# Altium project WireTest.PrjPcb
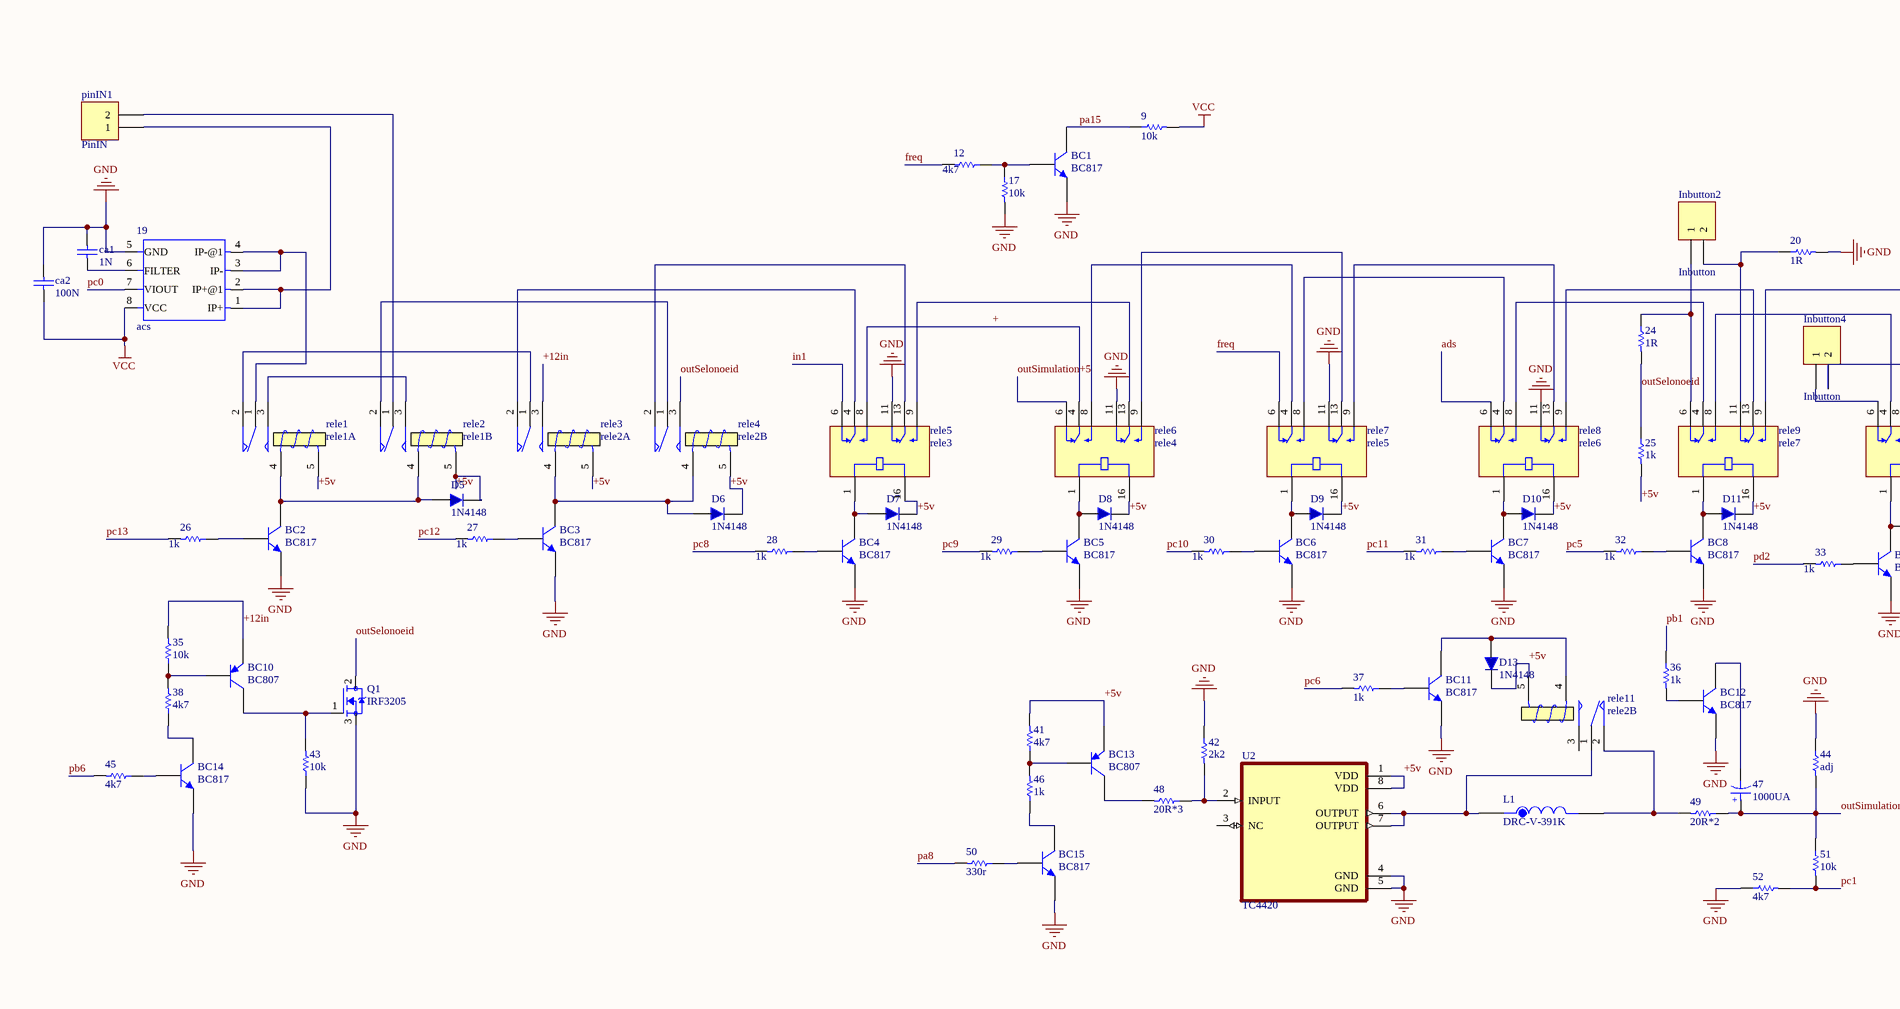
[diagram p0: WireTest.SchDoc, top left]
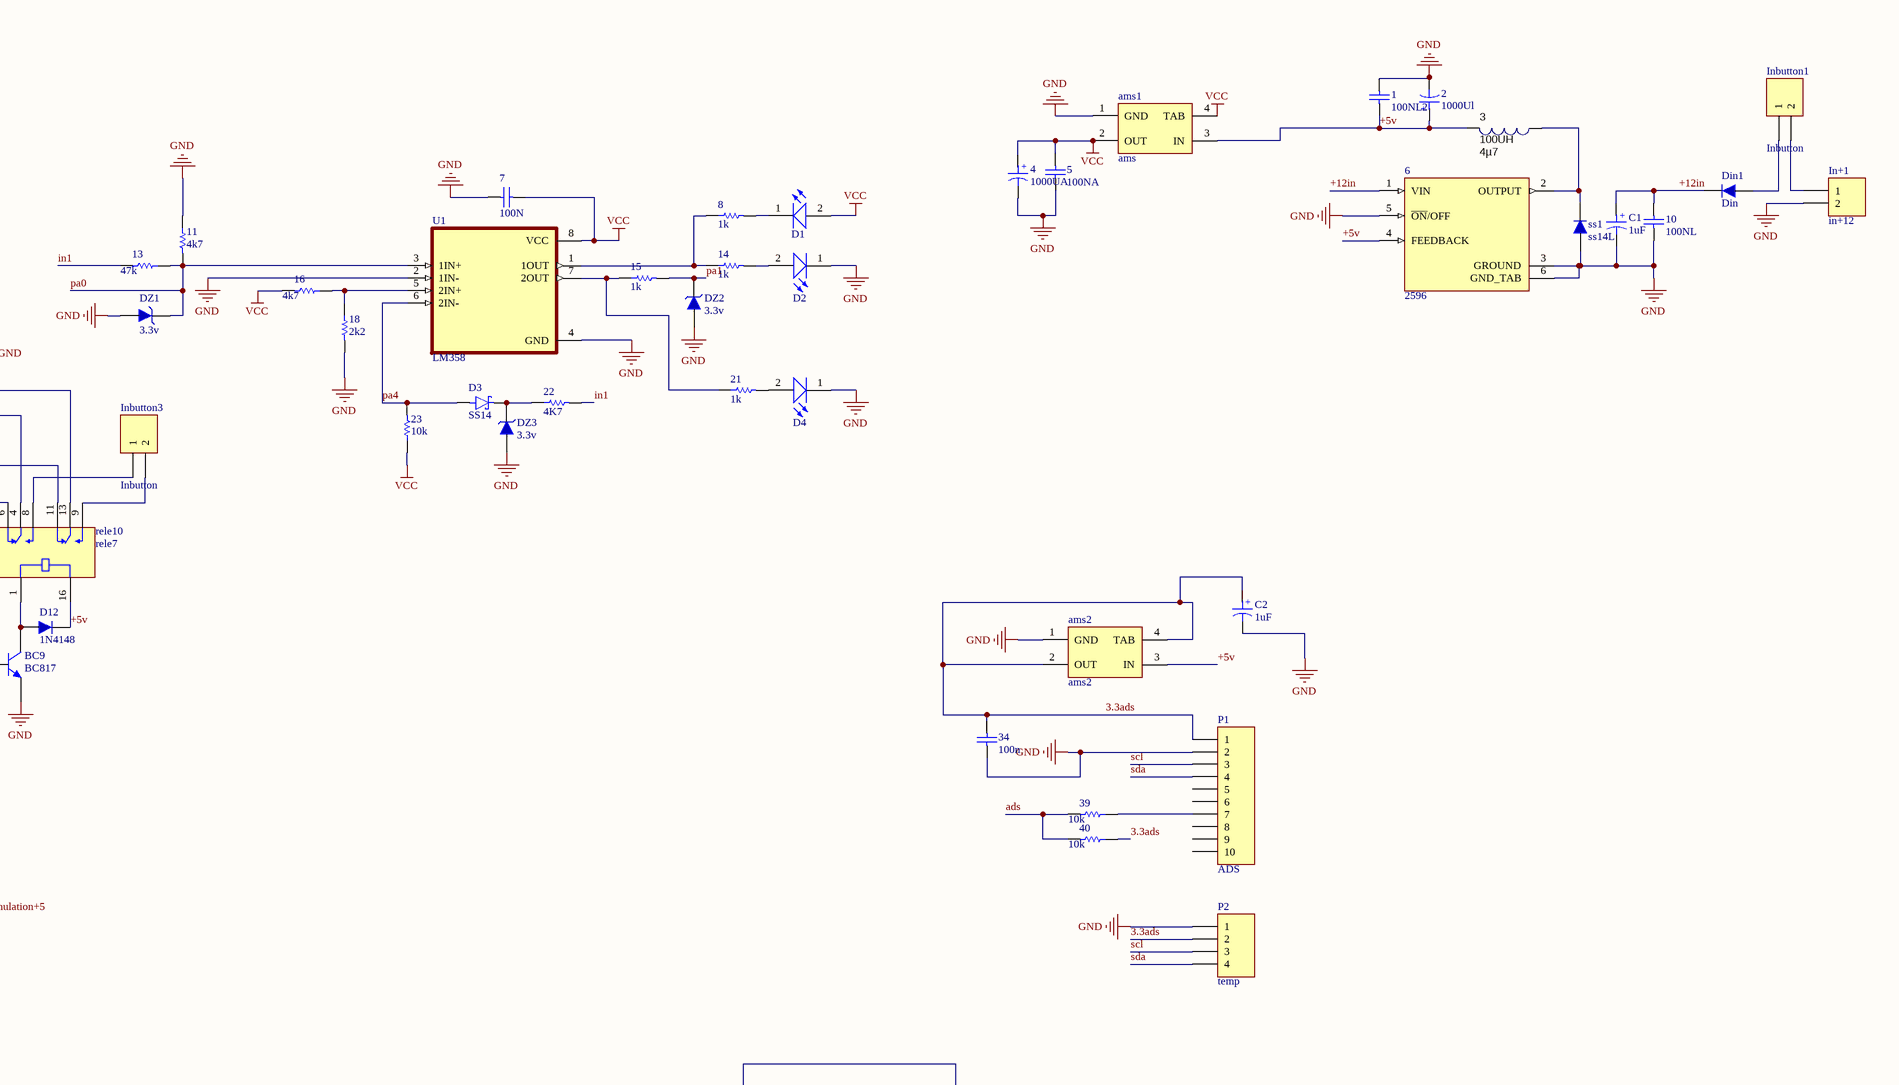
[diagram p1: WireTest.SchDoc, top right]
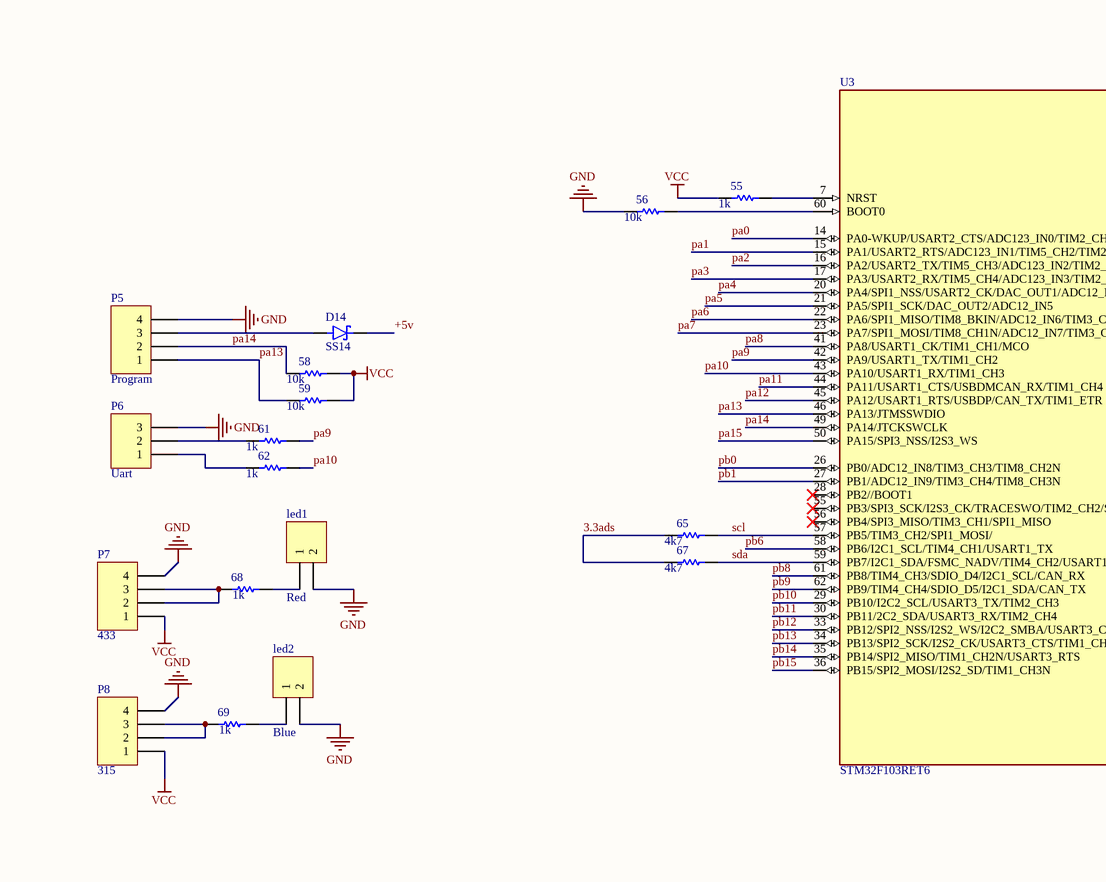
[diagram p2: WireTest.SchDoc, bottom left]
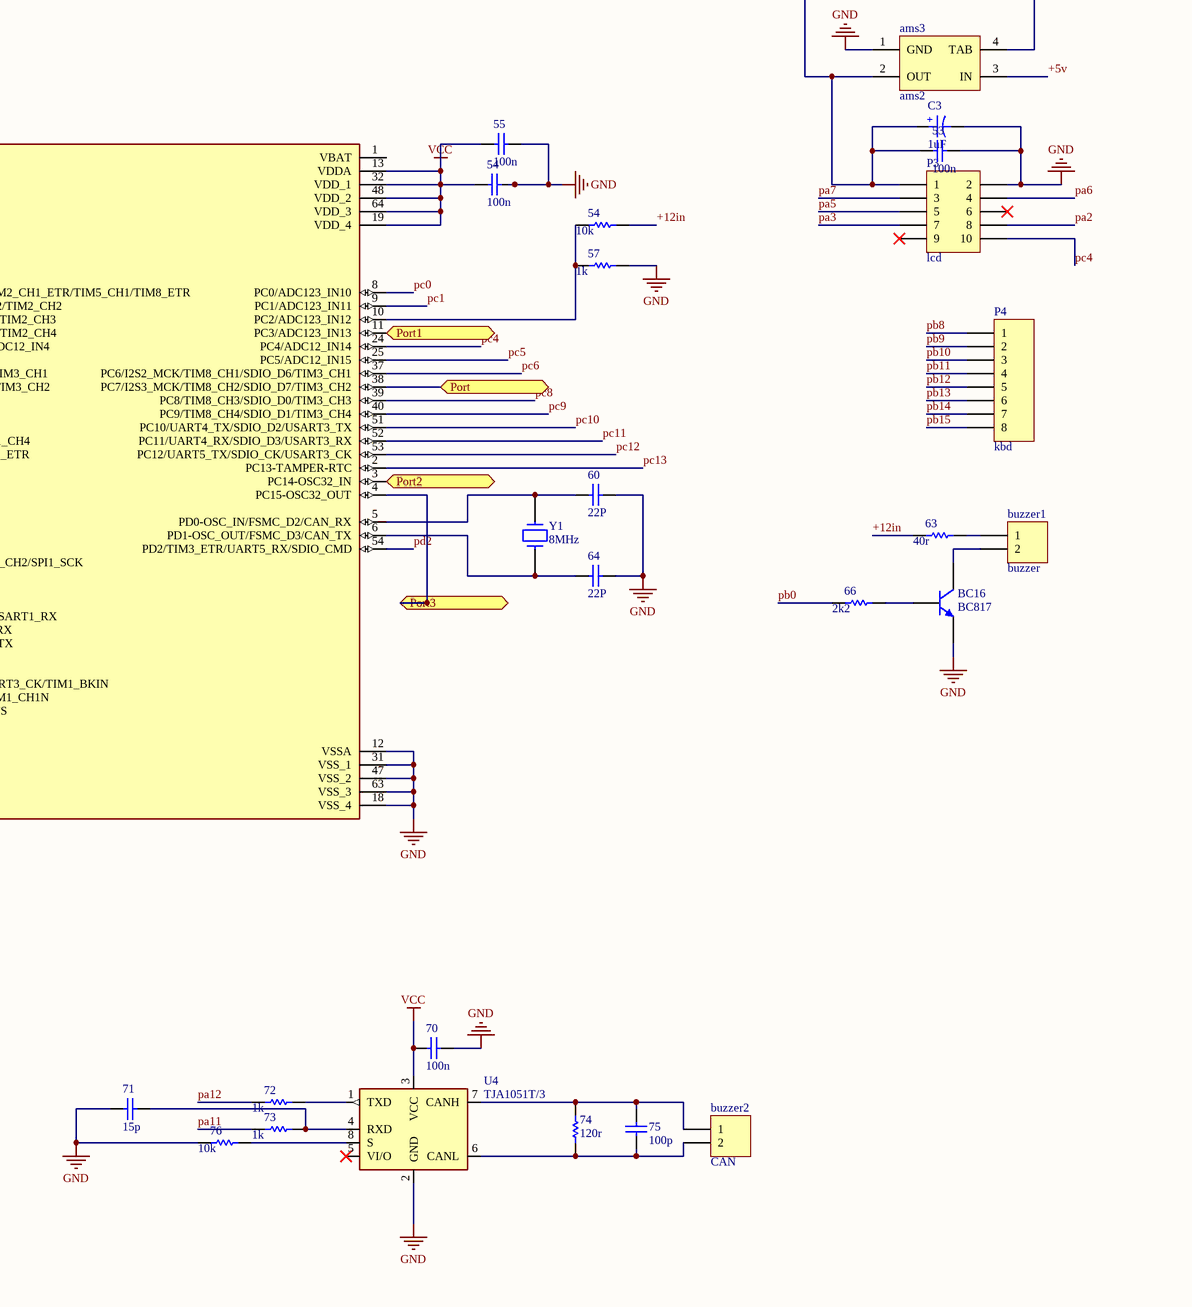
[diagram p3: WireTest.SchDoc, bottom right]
1 sheet, 157 parts. Net scope: flat (ports and power ports of the same name join across sheets).
Board file: wireTest.PcbDoc

## Sheet WireTest.SchDoc
size D

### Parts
(Parts that share a designator on the sheet are numbered #1, #2 ... from top to bottom, then left to right.)
1  100NL2  [CAPC3413X12N]
2  1000Ul  [Cap electrolitic radial 8x12-3.5]
3  100UH  value 4µ7  [Inductor SMD 3x3.2mm]
4  1000UA  [Cap electrolitic radial 8x12-3.5]
5  100NA  [CAPC3413X12N]
6  2596  [TO170P1524X483-6N]
7  100N  [CAPC3413X12N]
8  1k  [RESC4817X04N]
9  10k  [RESC4817X04N]
10  100NL  [CAPC3413X12N]
11  4k7  [RESC4817X04N]
12  4k7  [RESC4817X04N]
13  47k  [RESC4817X04N]
14  1k  [RESC4817X04N]
15  1k  [RESC4817X04N]
16  4k7  [RESC4817X04N]
17  10k  [RESC4817X04N]
18  2k2  [RESC4817X04N]
19  acs  [SOIC8-1.27-5X4MM]
20  1R  [RESC4817X04N]
21  1k  [RESC4817X04N]
22  4K7  [RESC4817X04N]
23  10k  [RESC4817X04N]
24  1R  [RESC4817X04N]
25  1k  [RESC4817X04N]
26  1k  [RESC4817X04N]
27  1k  [RESC4817X04N]
28  1k  [RESC4817X04N]
29  1k  [RESC4817X04N]
30  1k  [RESC4817X04N]
31  1k  [RESC4817X04N]
32  1k  [RESC4817X04N]
33  1k  [RESC4817X04N]
34  100n  [CAPC3413X12N]
35  10k  [RESC4817X04N]
36  1k  [RESC4817X04N]
37  1k  [RESC4817X04N]
38  4k7  [RESC4817X04N]
39  10k  [RESC4817X04N]
40  10k  [RESC4817X04N]
41  4k7  [RESC4817X04N]
42  2k2  [RESC4817X04N]
43  10k  [RESC4817X04N]
44  adj  [RESC4817X04N]
45  4k7  [RESC4817X04N]
46  1k  [RESC4817X04N]
47  1000UA  [Cap electrolitic radial 8x12-3.5]
48  20R*3  [RESC4817X04N]
49  20R*2  [RESC4817X04N]
50  330r  [RESC4817X04N]
51  10k  [RESC4817X04N]
52  4k7  [RESC4817X04N]
53  100n  [CAPC3413X12N]
54#1  100n  [CAPC3413X12N]
54#2  10k  [RESC4817X04N]
55#1  100n  [CAPC3413X12N]
55#2  1k  [RESC4817X04N]
56  10k  [RESC4817X04N]
57  1k  [RESC4817X04N]
58  10k  [RESC4817X04N]
59  10k  [RESC4817X04N]
60  22P  [CAPC3413X12N]
61  1k  [RESC4817X04N]
62  1k  [RESC4817X04N]
63  40r  [RESC4817X04N]
64  22P  [CAPC3413X12N]
65  4k7  [RESC4817X04N]
66  2k2  [RESC4817X04N]
67  4k7  [RESC4817X04N]
68  1k  [RESC4817X04N]
69  1k  [RESC4817X04N]
70  100n  [CAPC3413X12N]
71  15p  [CAPC3413X12N]
72  1k  [RESC4817X04N]
73  1k  [RESC4817X04N]
74  120r  [RESC4817X04N]
75  100p  [CAPC3413X12N]
76  10k  [RESC4817X04N]
ams1  ams  [MP04A_N]
ams2  ams2  [MP04A_N]
ams3  ams2  [MP04A_N]
BC1  BC817  [SOT23_N]
BC2  BC817  [SOT23_N]
BC3  BC817  [SOT23_N]
BC4  BC817  [SOT23_N]
BC5  BC817  [SOT23_N]
BC6  BC817  [SOT23_N]
BC7  BC817  [SOT23_N]
BC8  BC817  [SOT23_N]
BC9  BC817  [SOT23_N]
BC10  BC807  [SOT23_BEC_N]
BC11  BC817  [SOT23_N]
BC12  BC817  [SOT23_N]
BC13  BC807  [SOT23_BEC_N]
BC14  BC817  [SOT23_N]
BC15  BC817  [SOT23_N]
BC16  BC817  [SOT23_N]
buzzer1  buzzer  [HDR1X2]
buzzer2  CAN  [HDR1X2]
C1  1uF  [Cap electrolitic radial 8x12-3.5]
C2  1uF  [Cap1206_(3216X18L)Size A]
C3  1uF  [Cap1206_(3216X18L)Size A]
ca1  1N  [CAPC3413X12N]
ca2  100N  [CAPC3413X12N]
D1  led-  [LED_SMD_0805]  (value not drawn)
D2  led+  [LED_SMD_0805]  (value not drawn)
D3  SS14  [DIOM4325X250N]
D4  led_r  [LED_SMD_0805]  (value not drawn)
D5  1N4148  [Diode 1n4148 SMD]
D6  1N4148  [Diode 1n4148 SMD]
D7  1N4148  [Diode 1n4148 SMD]
D8  1N4148  [Diode 1n4148 SMD]
D9  1N4148  [Diode 1n4148 SMD]
D10  1N4148  [Diode 1n4148 SMD]
D11  1N4148  [Diode 1n4148 SMD]
D12  1N4148  [Diode 1n4148 SMD]
D13  1N4148  [Diode 1n4148 SMD]
D14  SS14  [DIOM4325X250N]
Din1  Din  [Diode 1W Stand]
DZ1  3.3v  [SOD80, LL-34]
DZ2  3.3v  [SOD80, LL-34]
DZ3  3.3v  [SOD80, LL-34]
In+1  in+12  [HDR1X2]
Inbutton1  Inbutton  [HDR1X2]
Inbutton2  Inbutton  [HDR1X2]
Inbutton3  Inbutton  [HDR1X2]
Inbutton4  Inbutton  [HDR1X2]
L1  DRC-V-391K  [IND_DRC-V-391K]
led1  Red  [HDR1X2]
led2  Blue  [HDR1X2]
P1  ADS  [HDR1X10]
P2  temp  [HDR1X4]
P3  lcd  [HDR2X5]
P4  kbd  [HDR1X8]
P5  Program  [HDR1X4]
P6  Uart  [HDR1X3]
P7  433  [HDR1X4]
P8  315  [HDR1X4]
pinIN1  PinIN  [HDR1X2]
Q1  IRF3205  [TO254P1067X483X3124-3P]
rele1  rele1A  [Relay 15.40x12.10x13.10]
rele2  rele1B  [Relay 15.40x12.10x13.10]
rele3  rele2A  [Relay 15.40x12.10x13.10]
rele4  rele2B  [Relay 15.40x12.10x13.10]
rele5  rele3  [RELAY_9-1393792-3]
rele6  rele4  [RELAY_9-1393792-3]
rele7  rele5  [RELAY_9-1393792-3]
rele8  rele6  [RELAY_9-1393792-3]
rele9  rele7  [RELAY_9-1393792-3]
rele10  rele7  [RELAY_9-1393792-3]
rele11  rele2B  [Relay 15.40x12.10x13.10]
ss1  ss14L  [Diode 1N4007 SMD]
U1  LM358  [SOIC127P599X175-8N]
U2  TC4420  [DIP787W46P254L927H533Q8]
U3  STM32F103RET6  [QFP50P1200X1200X160-64N]
U4  TJA1051T/3  [SOT96-1]
Y1  8MHz  [My_Crystal]

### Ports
Port, Port1, Port2, Port3

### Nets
GND: 1.2 2.2 4.2 5.1 6.3(GROUND) 6.5(~{ON}/OFF) 6.6(GND_TAB) 7.2 10.1 11.1 17.2 18.2 19.5(GND) 20.2 34.2 42.1 43.1 44.1 52.1 53.2 54#1.2 55#1.2 56.2 57.1 60.1 64.1 70.1 71.2 76.2 ams1.1(GND) ams2.1(GND) ams3.1(GND) BC1.2(E) BC2.2(E) BC3.2(E) BC4.2(E) BC5.2(E) BC6.2(E) BC7.2(E) BC8.2(E) BC9.2(E) BC11.2(E) BC12.2(E) BC14.2(E) BC15.2(E) BC16.2(E) C1.2 C2.2 C3.2 ca1.1 ca2.1 D2.1(K) D4.1(K) DZ1.1 DZ2.1 DZ3.1 In+1.2 led1.2 led2.2 P1.2 P2.1 P3.2 P5.4 P6.3 P7.4 P8.4 Q1.3(S) rele5.11(NC2) rele6.11(NC2) rele7.11(NC2) rele8.11(NC2) ss1.1 U1.2(1IN-) U1.4(GND) U2.4(GND) U2.5(GND) U3.12(VSSA) U3.18(VSS_4) U3.31(VSS_1) U3.47(VSS_2) U3.63(VSS_3) U4.2(GND)
VCC: 4.1 5.2 7.1 9.2 16.2 19.8(VCC) 23.1 54#1.1 55#1.1 55#2.2 58.1 59.1 70.2 ams1.2(OUT) ams1.4(TAB) ca2.2 D1.2(A) P7.1 P8.1 U1.8(VCC) U3.13(VDDA) U3.19(VDD_4) U3.32(VDD_1) U3.48(VDD_2) U3.64(VDD_3) U4.3(VCC)
3.3ads: 34.1 40.1 65.2 67.2 ams2.2(OUT) ams2.4(TAB) C2.1 P1.1 P2.2
+: rele5.8(NO1) rele6.4(COM1)
+5v: 1.1 2.1 3.2 6.4(FEEDBACK) 25.2 41.2 ams1.3(IN) ams2.3(IN) ams3.3(IN) BC13.2(E) D5.2 D6.2 D7.2 D8.2 D9.2 D10.2 D11.2 D12.2 D13.2 D14.C(K) rele1.5(T2) rele2.5(T2) rele3.5(T2) rele4.5(T2) rele5.16(COIL2) rele6.16(COIL2) rele7.16(COIL2) rele8.16(COIL2) rele9.16(COIL2) rele10.16(COIL2) rele11.5(T2) U2.1(VDD) U2.8(VDD)
+12in: 6.1(VIN) 10.2 35.2 54#2.1 63.2 BC10.2(E) C1.1 Din1.2 rele3.3(NO)
ads: 39.2 40.2 rele8.6(NC1)
freq: 12.2 rele7.6(NC1)
in1: 13.2 22.2 rele5.6(NC1)
outSelonoeid: 24.2 25.1 Q1.2(D) rele4.3(NO)
outSimulation+5: 44.2 47.1 49.1 51.1 rele6.6(NC1)
pa0: 11.2 13.1 DZ1.2 U1.3(1IN+) U3.14(PA0-WKUP/USART2_CTS/ADC123_IN0/TIM2_CH1_ETR/TIM5_CH1/TIM8_ETR)
pa1: 15.2 DZ2.2 U3.15(PA1/USART2_RTS/ADC123_IN1/TIM5_CH2/TIM2_CH2)
pa2: P3.8 U3.16(PA2/USART2_TX/TIM5_CH3/ADC123_IN2/TIM2_CH3)
pa3: P3.7 U3.17(PA3/USART2_RX/TIM5_CH4/ADC123_IN3/TIM2_CH4)
pa4: 23.2 D3.A U1.6(2IN-) U3.20(PA4/SPI1_NSS/USART2_CK/DAC_OUT1/ADC12_IN4)
pa5: P3.5 U3.21(PA5/SPI1_SCK/DAC_OUT2/ADC12_IN5)
pa6: P3.4 U3.22(PA6/SPI1_MISO/TIM8_BKIN/ADC12_IN6/TIM3_CH1)
pa7: P3.3 U3.23(PA7/SPI1_MOSI/TIM8_CH1N/ADC12_IN7/TIM3_CH2)
pa8: 50.2 U3.41(PA8/USART1_CK/TIM1_CH1/MCO)
pa9: 61.1 U3.42(PA9/USART1_TX/TIM1_CH2)
pa10: 62.1 U3.43(PA10/USART1_RX/TIM1_CH3)
pa11: 73.2 U3.44(PA11/USART1_CTS/USBDMCAN_RX/TIM1_CH4)
pa12: 72.2 U3.45(PA12/USART1_RTS/USBDP/CAN_TX/TIM1_ETR)
pa13: 59.2 P5.1 U3.46(PA13/JTMSSWDIO)
pa14: 58.2 P5.2 U3.49(PA14/JTCKSWCLK)
pa15: 9.1 BC1.3(C) U3.50(PA15/SPI3_NSS/I2S3_WS)
pb0: 66.2 U3.26(PB0/ADC12_IN8/TIM3_CH3/TIM8_CH2N)
pb1: 36.1 U3.27(PB1/ADC12_IN9/TIM3_CH4/TIM8_CH3N)
pb6: 45.2 U3.58(PB6/I2C1_SCL/TIM4_CH1/USART1_TX)
pb8: P4.1 U3.61(PB8/TIM4_CH3/SDIO_D4/I2C1_SCL/CAN_RX)
pb9: P4.2 U3.62(PB9/TIM4_CH4/SDIO_D5/I2C1_SDA/CAN_TX)
pb10: P4.3 U3.29(PB10/I2C2_SCL/USART3_TX/TIM2_CH3)
pb11: P4.4 U3.30(PB11/2C2_SDA/USART3_RX/TIM2_CH4)
pb12: P4.5 U3.33(PB12/SPI2_NSS/I2S2_WS/I2C2_SMBA/USART3_CK/TIM1_BKIN)
pb13: P4.6 U3.34(PB13/SPI2_SCK/I2S2_CK/USART3_CTS/TIM1_CH1N)
pb14: P4.7 U3.35(PB14/SPI2_MISO/TIM1_CH2N/USART3_RTS)
pb15: P4.8 U3.36(PB15/SPI2_MOSI/I2S2_SD/TIM1_CH3N)
pc0: 19.7(VIOUT) U3.8(PC0/ADC123_IN10)
pc1: 51.2 52.2 U3.9(PC1/ADC123_IN11)
pc4: P3.10 U3.24(PC4/ADC12_IN14)
pc5: 32.2 U3.25(PC5/ADC12_IN15)
pc6: 37.2 U3.37(PC6/I2S2_MCK/TIM8_CH1/SDIO_D6/TIM3_CH1)
pc8: 28.2 U3.39(PC8/TIM8_CH3/SDIO_D0/TIM3_CH3)
pc9: 29.2 U3.40(PC9/TIM8_CH4/SDIO_D1/TIM3_CH4)
pc10: 30.2 U3.51(PC10/UART4_TX/SDIO_D2/USART3_TX)
pc11: 31.2 U3.52(PC11/UART4_RX/SDIO_D3/USART3_RX)
pc12: 27.2 U3.53(PC12/UART5_TX/SDIO_CK/USART3_CK)
pc13: 26.2 U3.2(PC13-TAMPER-RTC)
pd2: 33.2 U3.54(PD2/TIM3_ETR/UART5_RX/SDIO_CMD)
scl: 65.1 P1.3 P2.3 U3.57(PB5/TIM3_CH2/SPI1_MOSI/)
sda: 67.1 P1.4 P2.4 U3.59(PB7/I2C1_SDA/FSMC_NADV/TIM4_CH2/USART1_RX)
Net3_1: 3.1 6.2(OUTPUT) ss1.2
Net8_1: 8.1 14.1 U1.1(1OUT)
Net8_2: 8.2 D1.1(K)
Net12_1: 12.1 17.1 BC1.1(B)
Net14_2: 14.2 D2.2(A)
Net15_1: 15.1 21.1 U1.7(2OUT)
Net16_1: 16.1 18.1 U1.5(2IN+)
Net19_1: 19.1(IP+) 19.2(IP+@1) pinIN1.1
Net19_3: 19.3(IP-) 19.4(IP-@1) rele1.1(COM)
Net19_6: 19.6(FILTER) ca1.2
Net20_1: 20.1 Inbutton2.2 rele9.11(NC2)
Net21_2: 21.2 D4.2(A)
Net22_1: 22.1 D3.C(K) DZ3.2
Net24_1: 24.1 Inbutton2.1 rele9.6(NC1)
Net26_1: 26.1 BC2.1(B)
Net27_1: 27.1 BC3.1(B)
Net28_1: 28.1 BC4.1(B)
Net29_1: 29.1 BC5.1(B)
Net30_1: 30.1 BC6.1(B)
Net31_1: 31.1 BC7.1(B)
Net32_1: 32.1 BC8.1(B)
Net33_1: 33.1 BC9.1(B)
Net35_1: 35.1 38.2 BC10.1(B)
Net36_2: 36.2 BC12.1(B)
Net37_1: 37.1 BC11.1(B)
Net38_1: 38.1 BC14.3(C)
Net39_1: 39.1 P1.7
Net41_1: 41.1 46.2 BC13.1(B)
Net42_2: 42.2 48.1 U2.2(INPUT)
Net43_2: 43.2 BC10.3(C) Q1.1(G)
Net45_1: 45.1 BC14.1(B)
Net46_1: 46.1 BC15.3(C)
Net47_2: 47.2 BC12.3(C)
Net48_2: 48.2 BC13.3(C)
Net49_2: 49.2 L1.2 rele11.2(NC)
Net50_1: 50.1 BC15.1(B)
Net53_1: 53.1 ams3.2(OUT) ams3.4(TAB) C3.1 P3.1
Net54#2_2: 54#2.2 57.2 U3.10(PC2/ADC123_IN12)
Net55#2_1: 55#2.1 U3.7(NRST)
Net56_1: 56.1 U3.60(BOOT0)
Net60_2: 60.2 U3.5(PD0-OSC_IN/FSMC_D2/CAN_RX) Y1.2
Net61_2: 61.2 P6.2
Net62_2: 62.2 P6.1
Net63_1: 63.1 buzzer1.1
Net64_2: 64.2 U3.6(PD1-OSC_OUT/FSMC_D3/CAN_TX) Y1.1
Net66_1: 66.1 BC16.1(B)
Net68_1: 68.1 led1.1
Net68_2: 68.2 P7.2 P7.3
Net69_1: 69.1 led2.1
Net69_2: 69.2 P8.2 P8.3
Net71_1: 71.1 73.1 U4.4(RXD)
Net72_1: 72.1 U4.1(TXD)
Net74_1: 74.1 75.2 buzzer2.1 U4.7(CANH)
Net74_2: 74.2 75.1 buzzer2.2 U4.6(CANL)
Net76_1: 76.1 U4.8(S)
NetBC2_3: BC2.3(C) D5.1 rele1.4(T1) rele2.4(T1)
NetBC3_3: BC3.3(C) D6.1 rele3.4(T1) rele4.4(T1)
NetBC4_3: BC4.3(C) D7.1 rele5.1(COIL1)
NetBC5_3: BC5.3(C) D8.1 rele6.1(COIL1)
NetBC6_3: BC6.3(C) D9.1 rele7.1(COIL1)
NetBC7_3: BC7.3(C) D10.1 rele8.1(COIL1)
NetBC8_3: BC8.3(C) D11.1 rele9.1(COIL1)
NetBC9_3: BC9.3(C) D12.1 rele10.1(COIL1)
NetBC11_3: BC11.3(C) D13.1 rele11.4(T1)
NetBC16_3: BC16.3(C) buzzer1.2
NetD14_A: D14.A P5.3
NetDin1_1: Din1.1 Inbutton1.1
NetIn+1_1: In+1.1 Inbutton1.2
NetInbutton3_1: Inbutton3.1 rele10.8(NO1)
NetInbutton3_2: Inbutton3.2 rele10.9(NO2)
NetInbutton4_1: Inbutton4.1 rele10.6(NC1)
NetInbutton4_2: Inbutton4.2 rele10.11(NC2)
NetL1_1: L1.1 rele11.1(COM) U2.6(OUTPUT) U2.7(OUTPUT)
NetpinIN1_2: pinIN1.2 rele2.1(COM)
Netrele1_2: rele1.2(NC) rele3.1(COM)
Netrele1_3: rele1.3(NO) rele2.3(NO)
Netrele2_2: rele2.2(NC) rele4.1(COM)
Netrele3_2: rele3.2(NC) rele5.4(COM1)
Netrele4_2: rele4.2(NC) rele5.13(COM2)
Netrele5_9: rele5.9(NO2) rele6.13(COM2)
Netrele6_8: rele6.8(NO1) rele7.4(COM1)
Netrele6_9: rele6.9(NO2) rele7.13(COM2)
Netrele7_8: rele7.8(NO1) rele8.4(COM1)
Netrele7_9: rele7.9(NO2) rele8.13(COM2)
Netrele8_8: rele8.8(NO1) rele9.4(COM1)
Netrele8_9: rele8.9(NO2) rele9.13(COM2)
Netrele9_8: rele9.8(NO1) rele10.4(COM1)
Netrele9_9: rele9.9(NO2) rele10.13(COM2)
NetU3_3: U3.3(PC14-OSC32_IN) ; port Port2
NetU3_4: U3.4(PC15-OSC32_OUT) ; port Port3
NetU3_11: U3.11(PC3/ADC123_IN13) ; port Port1
NetU3_38: U3.38(PC7/I2S3_MCK/TIM8_CH2/SDIO_D7/TIM3_CH2) ; port Port

Not connected (* = marked no-connect by the designer): P1 5 6 8 9 10; P3 6* 9*; rele11 3(NO); U2 3(NC); U3 1(VBAT) 28(PB2//BOOT1)* 55(PB3/SPI3_SCK/I2S3_CK/TRACESWO/TIM2_CH2/SPI1_SCK)* 56(PB4/SPI3_MISO/TIM3_CH1/SPI1_MISO)*; U4 5(VI/O)*

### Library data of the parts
1 5 7 10 34 53 54#1 55#1 60 64 70 71 75 ca1 ca2 = CAP SMD 0805: CAP 0805; Designer: Abbas Basereh
2 4 47 = Cap ELECTROLITIC TOTAL SIZE: Cap electrolitic radial; Designer: Abbas Basereh; VALUE: 1uF
3 = Inductor 4.7µH SMD 3x3.2mm: Tolerance: ±20%; SCDType: source
6 = LM2596S-5.0
8 9 11-18 20-33 35-46 48-52 54#2 55#2 56-59 61-63 65-69 72-74 76 = RES 1206 0.25W: RES 1206; Designer: Abbas Basereh; Desc.: RES SMD 1206
19 = CURRENT-ACS712ELCTR-05B-T(SOIC8-5X4MM): Current Sensor 5A 1 Channel Hall Effect, Open Loop Bidirectional 8-SOIC _0.154, 3.90mm Width_; MF: Allegro
ams1-ams3 = LM1117IMP-x.x: x.x Volt, 800mA Low-Dropout Linear Regulator, 4-pin SOT-223; PartNumber: LM1117IMP-3.3; Manufacturer: National Semiconductor; PackageTopMarking: XYTT*N05B; PowerWise: N; CompType: LDO IC
BC1-BC9 BC11 BC12 BC14-BC16 = BC817: 45 V, 500 mA NPN general-purpose transistors
BC10 BC13 = BC807: PNP General-purpose Transistor
buzzer1 buzzer2 In+1 Inbutton1-Inbutton4 led1 led2 pinIN1 = Header 2: Header, 2-Pin
C1-C3 = Cap ELECTROLITIC TOTAL SIZE: Cap electrolitic radial; Designer: Abbas Basereh
D1 D2 D4 = LED SMD PACKAGE: SMD Mono-color Chip LED Waterclear; Part Number: 150080BS75000; Peak Wavelength: 465 nm; Forward Voltage: 3.2 V
D5-D13 = 1N4148 SMD: General Semicoductor
Din1 ss1 = Diode DIP Package
DZ1-DZ3 = ZENER GENERAL DIODE: DIODE ZENER GENERAL; VALUE: 12V
L1 = DRC-V-391K: Radial Coil Inductor; MF: Bel Fuse
P1 = Header 10: Header, 10-Pin
P2 P5 P7 P8 = Header 4: Header, 4-Pin
P3 = Header 5X2: Header, 5-Pin, Dual row
P4 = Header 8: Header, 8-Pin
P6 = Header 3: Header, 3-Pin
Q1 = IRF3205PBF: N-Channel 55V 110A _Tc_ 200W _Tc_ Through Hole TO-220AB; MF: Infineon Technologies
rele1-rele4 rele11 = RELAY General: Relay_SPDT POWER NEEDLE; Designer: Ali Hafizi; Company: E.P.I.L
rele5-rele10 = V23105A5301A201: Industrial Control, Relays, I/O Modules, spdt, relay, Relays and Accessories; MF: TE Connectivity; MP: V23105-A5301-A201
U1 = LM358DRG3: Dual, 30-V, 700-kHz operational amplifier; MF: Texas Instruments
U2 = TC4420CPA: Microchip MOSFET Power Driver 6A 4.5 to 18V Non-Inverting 8-Pin PDIP ¦ Microchip Technology Inc. TC4420CPA
U3 = STM32F103RET6: ARMÂ® CortexÂ®-M3 STM32F1 Microcontroller IC 32-Bit 72MHz 512KB (512K x 8) FLASH 64-LQFP (10x10); MF: STMicroelectronics
U4 = TJA1051T/3: 1/1 ÐŸÑ€Ð¸ÐµÐ¼Ð¾Ð¿ÐµÑ€ÐµÐ´Ð°Ñ‚Ñ‡Ð¸Ðº ÐŸÐ¾Ð»Ð¾Ð²Ð¸Ð½Ð° CANbus 8-SO; MF: NXP USA
Y1 = CRYSTAL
